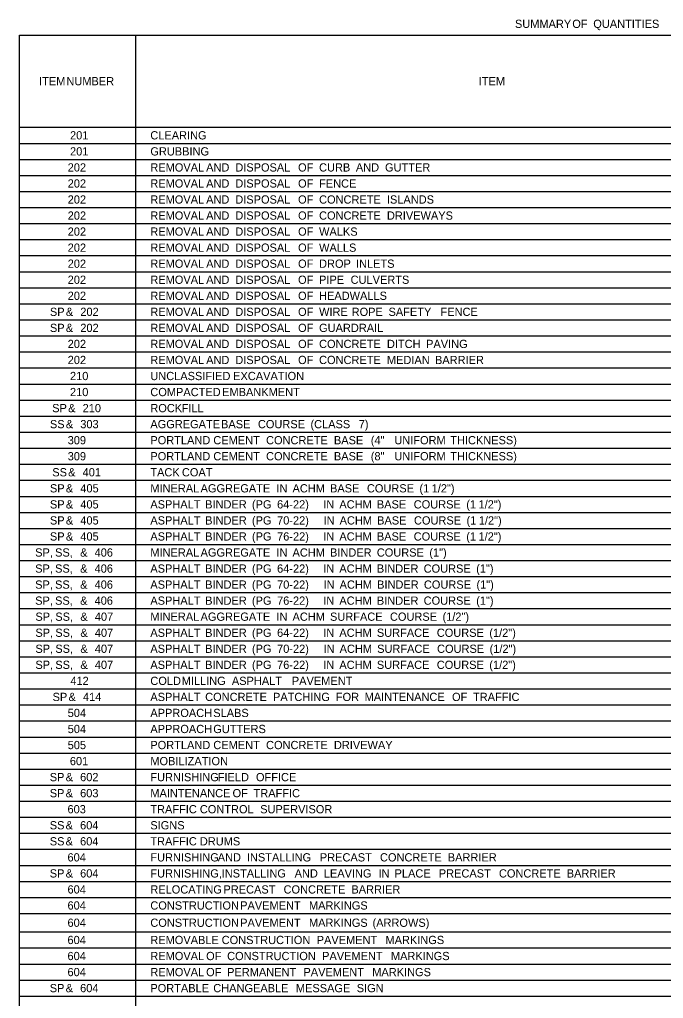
# Model space of a CAD drawing. Extents: x 1226603 to 1228117, y 151305 to 152343.
# Drawn here: x 1226606 to 1226938, y 151837 to 152343 of the extents above; entities that cross this region are included whole.
import ezdxf

# ---------------------------------------------------------------- set-up
doc = ezdxf.new("R2010")
doc.units = 0
doc.layers.add('R_Dimension', color=7, linetype='Continuous')

msp = doc.modelspace()

# ---------------------------------------------------------------- linework, layer by layer
at = {"layer": 'R_Dimension'}
for p, q in [((1226605.78, 152334.72), (1227235.63, 152334.72)), ((1226605.78, 151338.98), (1226605.78, 152334.72)), ((1226665.86, 151338.98), (1226665.86, 152334.72)), ((1226605.78, 152287.07), (1227235.63, 152287.07)), ((1226605.78, 152278.78), (1227235.63, 152278.78)), ((1226605.78, 152270.49), (1227235.63, 152270.49)), ((1226605.78, 152262.2), (1227235.63, 152262.2)), ((1226605.78, 152253.92), (1227235.63, 152253.92)), ((1226605.78, 152245.63), (1227235.63, 152245.63)), ((1226605.78, 152237.34), (1227235.63, 152237.34)), ((1226605.78, 152229.05), (1227235.63, 152229.05)), ((1226605.78, 152220.77), (1227235.63, 152220.77)), ((1226605.78, 152212.48), (1227235.63, 152212.48)), ((1226605.78, 152204.19), (1227235.63, 152204.19)), ((1226605.78, 152195.9), (1227235.63, 152195.9)), ((1226605.78, 152187.62), (1227235.63, 152187.62)), ((1226605.78, 152179.33), (1227235.63, 152179.33)), ((1226605.78, 152171.04), (1227235.63, 152171.04)), ((1226605.78, 152162.75), (1227235.63, 152162.75)), ((1226605.78, 152154.47), (1227235.63, 152154.47)), ((1226605.78, 152146.18), (1227235.63, 152146.18)), ((1226605.78, 152137.89), (1227235.63, 152137.89)), ((1226605.78, 152129.6), (1227235.63, 152129.6)), ((1226605.78, 152121.32), (1227235.63, 152121.32)), ((1226605.78, 152113.03), (1227235.63, 152113.03)), ((1226605.78, 152104.74), (1227235.63, 152104.74)), ((1226605.78, 152096.45), (1227235.63, 152096.45)), ((1226605.78, 152088.17), (1227235.63, 152088.17)), ((1226605.78, 152079.88), (1227235.63, 152079.88)), ((1226605.78, 152071.59), (1227235.63, 152071.59)), ((1226605.78, 152063.3), (1227235.63, 152063.3)), ((1226605.78, 152055.02), (1227235.63, 152055.02)), ((1226605.78, 152046.73), (1227235.63, 152046.73)), ((1226605.78, 152038.44), (1227235.63, 152038.44)), ((1226605.78, 152030.15), (1227235.63, 152030.15)), ((1226605.78, 152021.87), (1227235.63, 152021.87)), ((1226605.78, 152013.58), (1227235.63, 152013.58)), ((1226605.78, 152005.29), (1227235.63, 152005.29)), ((1226605.78, 151997), (1227235.63, 151997)), ((1226605.78, 151988.72), (1227235.63, 151988.72)), ((1226605.78, 151980.43), (1227235.63, 151980.43)), ((1226605.78, 151972.14), (1227235.63, 151972.14)), ((1226605.78, 151963.85), (1227235.63, 151963.85)), ((1226605.78, 151955.57), (1227235.63, 151955.57)), ((1226605.78, 151947.28), (1227235.63, 151947.28)), ((1226605.78, 151938.99), (1227235.63, 151938.99)), ((1226605.78, 151930.7), (1227235.63, 151930.7)), ((1226605.78, 151922.42), (1227235.63, 151922.42)), ((1226605.78, 151914.13), (1227235.63, 151914.13)), ((1226605.78, 151905.84), (1227235.63, 151905.84)), ((1226605.78, 151897.55), (1227235.63, 151897.55)), ((1226605.78, 151889.27), (1227235.63, 151889.27)), ((1226605.78, 151880.98), (1227235.63, 151880.98)), ((1226605.78, 151871.45), (1227235.63, 151871.45)), ((1226605.78, 151863.16), (1227235.63, 151863.16)), ((1226605.78, 151854.87), (1227235.63, 151854.87)), ((1226605.78, 151846.58), (1227235.63, 151846.58)), ((1226605.78, 151838.3), (1227235.63, 151838.3))]:
    msp.add_line(p, q, dxfattribs=at)

# ---------------------------------------------------------------- texts
for s, p in [('SUMMARY', (1226861.64, 152338.39)), (' OF', (1226889.68, 152338.39)), (' QUANTITIES', (1226900.52, 152338.39)), ('ITEM', (1226615.87, 152308.77)), (' NUMBER', (1226628.39, 152308.77)), ('ITEM', (1226842.96, 152308.77)), ('201', (1226631.84, 152280.8)), ('CLEARING', (1226673.32, 152280.8)), ('201', (1226631.84, 152272.51)), ('GRUBBING', (1226673.32, 152272.51)), ('202', (1226630.63, 152264.22)), ('REMOVAL', (1226673.32, 152264.22)), (' AND', (1226700.56, 152264.22)), (' DISPOSAL', (1226715.62, 152264.22)), (' OF', (1226748.05, 152264.22)), (' CURB', (1226758.89, 152264.22)), (' AND', (1226777.9, 152264.22)), (' GUTTER', (1226792.96, 152264.22)), ('202', (1226630.63, 152255.93)), ('REMOVAL', (1226673.32, 152255.93)), (' AND', (1226700.56, 152255.93)), (' DISPOSAL', (1226715.62, 152255.93)), (' OF', (1226748.05, 152255.93)), (' FENCE', (1226758.89, 152255.93)), ('202', (1226630.63, 152247.65)), ('REMOVAL', (1226673.32, 152247.65)), (' AND', (1226700.56, 152247.65)), (' DISPOSAL', (1226715.62, 152247.65)), (' OF', (1226748.05, 152247.65)), (' CONCRETE', (1226758.89, 152247.65)), (' ISLANDS', (1226793.93, 152247.65)), ('202', (1226630.63, 152239.36)), ('REMOVAL', (1226673.32, 152239.36)), (' AND', (1226700.56, 152239.36)), (' DISPOSAL', (1226715.62, 152239.36)), (' OF', (1226748.05, 152239.36)), (' CONCRETE', (1226758.89, 152239.36)), (' DRIVEWAYS', (1226793.93, 152239.36)), ('202', (1226630.63, 152231.07)), ('REMOVAL', (1226673.32, 152231.07)), (' AND', (1226700.56, 152231.07)), (' DISPOSAL', (1226715.62, 152231.07)), (' OF', (1226748.05, 152231.07)), (' WALKS', (1226758.89, 152231.07)), ('202', (1226630.63, 152222.78)), ('REMOVAL', (1226673.32, 152222.78)), (' AND', (1226700.56, 152222.78)), (' DISPOSAL', (1226715.62, 152222.78)), (' OF', (1226748.05, 152222.78)), (' WALLS', (1226758.89, 152222.78)), ('202', (1226630.63, 152214.5)), ('REMOVAL', (1226673.32, 152214.5)), (' AND', (1226700.56, 152214.5)), (' DISPOSAL', (1226715.62, 152214.5)), (' OF', (1226748.05, 152214.5)), (' DROP', (1226758.89, 152214.5)), (' INLETS', (1226777.96, 152214.5)), ('202', (1226630.63, 152206.21)), ('REMOVAL', (1226673.32, 152206.21)), (' AND', (1226700.56, 152206.21)), (' DISPOSAL', (1226715.62, 152206.21)), (' OF', (1226748.05, 152206.21)), (' PIPE', (1226758.89, 152206.21)), (' CULVERTS', (1226775.19, 152206.21)), ('202', (1226630.63, 152197.92)), ('REMOVAL', (1226673.32, 152197.92)), (' AND', (1226700.56, 152197.92)), (' DISPOSAL', (1226715.62, 152197.92)), (' OF', (1226748.05, 152197.92)), (' HEADWALLS', (1226758.89, 152197.92)), ('SP', (1226621.45, 152189.63)), (' &', (1226628.11, 152189.63)), (' 202', (1226635.57, 152189.63)), ('REMOVAL', (1226673.32, 152189.63)), (' AND', (1226700.56, 152189.63)), (' DISPOSAL', (1226715.62, 152189.63)), (' OF', (1226748.05, 152189.63)), (' WIRE', (1226758.89, 152189.63)), (' ROPE', (1226775.72, 152189.63)), (' SAFETY', (1226794.76, 152189.63)), (' FENCE', (1226821.63, 152189.63)), ('SP', (1226621.45, 152181.35)), (' &', (1226628.11, 152181.35)), (' 202', (1226635.57, 152181.35)), ('REMOVAL', (1226673.32, 152181.35)), (' AND', (1226700.56, 152181.35)), (' DISPOSAL', (1226715.62, 152181.35)), (' OF', (1226748.05, 152181.35)), (' GUARDRAIL', (1226758.89, 152181.35)), ('202', (1226630.63, 152173.06)), ('REMOVAL', (1226673.32, 152173.06)), (' AND', (1226700.56, 152173.06)), (' DISPOSAL', (1226715.62, 152173.06)), (' OF', (1226748.05, 152173.06)), (' CONCRETE', (1226758.89, 152173.06)), (' DITCH', (1226793.93, 152173.06)), (' PAVING', (1226814.17, 152173.06)), ('202', (1226630.63, 152164.77)), ('REMOVAL', (1226673.32, 152164.77)), (' AND', (1226700.56, 152164.77)), (' DISPOSAL', (1226715.62, 152164.77)), (' OF', (1226748.05, 152164.77)), (' CONCRETE', (1226758.89, 152164.77)), (' MEDIAN', (1226793.93, 152164.77)), (' BARRIER', (1226818.76, 152164.77)), ('210', (1226631.82, 152156.48)), ('UNCLASSIFIED', (1226673.32, 152156.48)), (' EXCAVATION', (1226714.51, 152156.48)), ('210', (1226631.82, 152148.2)), ('COMPACTED', (1226673.32, 152148.2)), (' EMBANKMENT', (1226708.83, 152148.2)), ('SP', (1226622.63, 152139.91)), (' &', (1226629.29, 152139.91)), (' 210', (1226636.76, 152139.91)), ('ROCK', (1226673.32, 152139.91)), (' FILL', (1226687.91, 152139.91)), ('SS', (1226621.46, 152131.62)), (' &', (1226628.09, 152131.62)), (' 303', (1226635.55, 152131.62)), ('AGGREGATE', (1226673.32, 152131.62)), (' BASE', (1226708.26, 152131.62)), (' COURSE', (1226727.3, 152131.62)), (' (CLASS', (1226754.44, 152131.62)), (' 7)', (1226779.37, 152131.62)), ('309', (1226630.62, 152123.33)), ('PORTLAND', (1226673.32, 152123.33)), (' CEMENT', (1226704.27, 152123.33)), (' CONCRETE', (1226731.51, 152123.33)), (' BASE', (1226766.55, 152123.33)), (' (4"', (1226785.59, 152123.33)), (' UNIFORM', (1226797.77, 152123.33)), (' THICKNESS)', (1226826.65, 152123.33)), ('309', (1226630.62, 152115.05)), ('PORTLAND', (1226673.32, 152115.05)), (' CEMENT', (1226704.27, 152115.05)), (' CONCRETE', (1226731.51, 152115.05)), (' BASE', (1226766.55, 152115.05)), (' (8"', (1226785.59, 152115.05)), (' UNIFORM', (1226797.77, 152115.05)), (' THICKNESS)', (1226826.65, 152115.05)), ('SS', (1226622.67, 152106.76)), (' &', (1226629.29, 152106.76)), (' 401', (1226636.76, 152106.76)), ('TACK', (1226673.32, 152106.76)), (' COAT', (1226688.04, 152106.76)), ('SP', (1226621.45, 152098.47)), (' &', (1226628.11, 152098.47)), (' 405', (1226635.57, 152098.47)), ('MINERAL', (1226673.32, 152098.47)), (' AGGREGATE', (1226697.68, 152098.47)), (' IN', (1226736.87, 152098.47)), (' ACHM', (1226745.17, 152098.47)), (' BASE', (1226764.54, 152098.47)), (' COURSE', (1226783.59, 152098.47)), (' (1', (1226810.73, 152098.47)), (' 1/2")', (1226817.05, 152098.47)), ('SP', (1226621.45, 152090.18)), (' &', (1226628.11, 152090.18)), (' 405', (1226635.57, 152090.18)), ('ASPHALT', (1226673.32, 152090.18)), (' BINDER', (1226700.06, 152090.18)), (' (PG', (1226724.22, 152090.18)), (' 64-22)', (1226737.2, 152090.18)), (' IN', (1226761.06, 152090.18)), (' ACHM', (1226769.36, 152090.18)), (' BASE', (1226788.74, 152090.18)), (' COURSE', (1226807.78, 152090.18)), (' (1', (1226834.92, 152090.18)), (' 1/2")', (1226841.25, 152090.18)), ('SP', (1226621.45, 152081.9)), (' &', (1226628.11, 152081.9)), (' 405', (1226635.57, 152081.9)), ('ASPHALT', (1226673.32, 152081.9)), (' BINDER', (1226700.06, 152081.9)), (' (PG', (1226724.22, 152081.9)), (' 70-22)', (1226737.2, 152081.9)), (' IN', (1226761.2, 152081.9)), (' ACHM', (1226769.5, 152081.9)), (' BASE', (1226788.87, 152081.9)), (' COURSE', (1226807.91, 152081.9)), (' (1', (1226835.05, 152081.9)), (' 1/2")', (1226841.38, 152081.9)), ('SP', (1226621.45, 152073.61)), (' &', (1226628.11, 152073.61)), (' 405', (1226635.57, 152073.61)), ('ASPHALT', (1226673.32, 152073.61)), (' BINDER', (1226700.06, 152073.61)), (' (PG', (1226724.22, 152073.61)), (' 76-22)', (1226737.2, 152073.61)), (' IN', (1226761.06, 152073.61)), (' ACHM', (1226769.36, 152073.61)), (' BASE', (1226788.74, 152073.61)), (' COURSE', (1226807.78, 152073.61)), (' (1', (1226834.92, 152073.61)), (' 1/2")', (1226841.25, 152073.61)), ('SP,', (1226613.83, 152065.32)), (' SS,', (1226622.53, 152065.32)), (' &', (1226635.48, 152065.32)), (' 406', (1226642.95, 152065.32)), ('MINERAL', (1226673.32, 152065.32)), (' AGGREGATE', (1226697.68, 152065.32)), (' IN', (1226736.87, 152065.32)), (' ACHM', (1226745.17, 152065.32)), (' BINDER', (1226764.54, 152065.32)), (' COURSE', (1226788.71, 152065.32)), (' (1")', (1226815.85, 152065.32)), ('SP,', (1226613.83, 152057.03)), (' SS,', (1226622.53, 152057.03)), (' &', (1226635.48, 152057.03)), (' 406', (1226642.95, 152057.03)), ('ASPHALT', (1226673.32, 152057.03)), (' BINDER', (1226700.06, 152057.03)), (' (PG', (1226724.22, 152057.03)), (' 64-22)', (1226737.2, 152057.03)), (' IN', (1226761.06, 152057.03)), (' ACHM', (1226769.36, 152057.03)), (' BINDER', (1226788.74, 152057.03)), (' COURSE', (1226812.9, 152057.03)), (' (1")', (1226840.04, 152057.03)), ('SP,', (1226613.83, 152048.75)), (' SS,', (1226622.53, 152048.75)), (' &', (1226635.48, 152048.75)), (' 406', (1226642.95, 152048.75)), ('ASPHALT', (1226673.32, 152048.75)), (' BINDER', (1226700.06, 152048.75)), (' (PG', (1226724.22, 152048.75)), (' 70-22)', (1226737.2, 152048.75)), (' IN', (1226761.2, 152048.75)), (' ACHM', (1226769.5, 152048.75)), (' BINDER', (1226788.87, 152048.75)), (' COURSE', (1226813.03, 152048.75)), (' (1")', (1226840.17, 152048.75)), ('SP,', (1226613.83, 152040.46)), (' SS,', (1226622.53, 152040.46)), (' &', (1226635.48, 152040.46)), (' 406', (1226642.95, 152040.46)), ('ASPHALT', (1226673.32, 152040.46)), (' BINDER', (1226700.06, 152040.46)), (' (PG', (1226724.22, 152040.46)), (' 76-22)', (1226737.2, 152040.46)), (' IN', (1226761.06, 152040.46)), (' ACHM', (1226769.36, 152040.46)), (' BINDER', (1226788.74, 152040.46)), (' COURSE', (1226812.9, 152040.46)), (' (1")', (1226840.04, 152040.46)), ('SP,', (1226613.95, 152032.17)), (' SS,', (1226622.65, 152032.17)), (' &', (1226635.6, 152032.17)), (' 407', (1226643.06, 152032.17)), ('MINERAL', (1226673.32, 152032.17)), (' AGGREGATE', (1226697.68, 152032.17)), (' IN', (1226736.87, 152032.17)), (' ACHM', (1226745.17, 152032.17)), (' SURFACE', (1226764.54, 152032.17)), (' COURSE', (1226795.5, 152032.17)), (' (1/2")', (1226822.64, 152032.17)), ('SP,', (1226613.95, 152023.88)), (' SS,', (1226622.65, 152023.88)), (' &', (1226635.6, 152023.88)), (' 407', (1226643.06, 152023.88)), ('ASPHALT', (1226673.32, 152023.88)), (' BINDER', (1226700.06, 152023.88)), (' (PG', (1226724.22, 152023.88)), (' 64-22)', (1226737.2, 152023.88)), (' IN', (1226761.06, 152023.88)), (' ACHM', (1226769.36, 152023.88)), (' SURFACE', (1226788.74, 152023.88)), (' COURSE', (1226819.69, 152023.88)), (' (1/2")', (1226846.83, 152023.88)), ('SP,', (1226613.95, 152015.6)), (' SS,', (1226622.65, 152015.6)), (' &', (1226635.6, 152015.6)), (' 407', (1226643.06, 152015.6)), ('ASPHALT', (1226673.32, 152015.6)), (' BINDER', (1226700.06, 152015.6)), (' (PG', (1226724.22, 152015.6)), (' 70-22)', (1226737.2, 152015.6)), (' IN', (1226761.2, 152015.6)), (' ACHM', (1226769.5, 152015.6)), (' SURFACE', (1226788.87, 152015.6)), (' COURSE', (1226819.83, 152015.6)), (' (1/2")', (1226846.97, 152015.6)), ('SP,', (1226613.95, 152007.31)), (' SS,', (1226622.65, 152007.31)), (' &', (1226635.6, 152007.31)), (' 407', (1226643.06, 152007.31)), ('ASPHALT', (1226673.32, 152007.31)), (' BINDER', (1226700.06, 152007.31)), (' (PG', (1226724.22, 152007.31)), (' 76-22)', (1226737.2, 152007.31)), (' IN', (1226761.06, 152007.31)), (' ACHM', (1226769.36, 152007.31)), (' SURFACE', (1226788.74, 152007.31)), (' COURSE', (1226819.69, 152007.31)), (' (1/2")', (1226846.83, 152007.31)), ('412', (1226632, 151999.02)), ('COLD', (1226673.32, 151999.02)), (' MILLING', (1226687.94, 151999.02)), (' ASPHALT', (1226713.85, 151999.02)), (' PAVEMENT', (1226744.83, 151999.02)), ('SP', (1226622.82, 151990.73)), (' &', (1226629.48, 151990.73)), (' 414', (1226636.94, 151990.73)), ('ASPHALT', (1226673.32, 151990.73)), (' CONCRETE', (1226700.06, 151990.73)), (' PATCHING', (1226735.1, 151990.73)), (' FOR', (1226767.56, 151990.73)), (' MAINTENANCE', (1226782.41, 151990.73)), (' OF', (1226827.56, 151990.73)), (' TRAFFIC', (1226838.4, 151990.73)), ('504', (1226630.63, 151982.45)), ('APPROACH', (1226673.32, 151982.45)), (' SLABS', (1226704.24, 151982.45)), ('504', (1226630.63, 151974.16)), ('APPROACH', (1226673.32, 151974.16)), (' GUTTERS', (1226704.24, 151974.16)), ('505', (1226630.63, 151965.87)), ('PORTLAND', (1226673.32, 151965.87)), (' CEMENT', (1226704.27, 151965.87)), (' CONCRETE', (1226731.51, 151965.87)), (' DRIVEWAY', (1226766.55, 151965.87)), ('601', (1226631.74, 151957.58)), ('MOBILIZATION', (1226673.32, 151957.58)), ('SP', (1226621.35, 151949.3)), (' &', (1226628.01, 151949.3)), (' 602', (1226635.47, 151949.3)), ('FURNISHING', (1226673.32, 151949.3)), (' FIELD', (1226706.55, 151949.3)), (' OFFICE', (1226726.29, 151949.3)), ('SP', (1226621.35, 151941.01)), (' &', (1226628.01, 151941.01)), (' 603', (1226635.47, 151941.01)), ('MAINTENANCE', (1226673.32, 151941.01)), (' OF', (1226714.21, 151941.01)), (' TRAFFIC', (1226725.06, 151941.01)), ('603', (1226630.53, 151932.72)), ('TRAFFIC', (1226673.32, 151932.72)), (' CONTROL', (1226697.31, 151932.72)), (' SUPERVISOR', (1226728.47, 151932.72)), ('SS', (1226621.36, 151924.43)), (' &', (1226627.99, 151924.43)), (' 604', (1226635.45, 151924.43)), ('SIGNS', (1226673.32, 151924.43)), ('SS', (1226621.36, 151916.15)), (' &', (1226627.99, 151916.15)), (' 604', (1226635.45, 151916.15)), ('TRAFFIC', (1226673.32, 151916.15)), (' DRUMS', (1226697.31, 151916.15)), ('604', (1226630.53, 151907.86)), ('FURNISHING', (1226673.32, 151907.86)), (' AND', (1226706.55, 151907.86)), (' INSTALLING', (1226721.61, 151907.86)), (' PRECAST', (1226759.29, 151907.86)), (' CONCRETE', (1226790.35, 151907.86)), (' BARRIER', (1226825.38, 151907.86)), ('SP', (1226621.35, 151899.57)), (' &', (1226628.01, 151899.57)), (' 604', (1226635.47, 151899.57)), ('FURNISHING,', (1226673.32, 151899.57)), (' INSTALLING', (1226708.59, 151899.57)), (' AND', (1226746.27, 151899.57)), (' LEAVING', (1226761.33, 151899.57)), (' IN', (1226789.58, 151899.57)), (' PLACE', (1226797.88, 151899.57)), (' PRECAST', (1226820.73, 151899.57)), (' CONCRETE', (1226851.79, 151899.57)), (' BARRIER', (1226886.82, 151899.57)), ('604', (1226630.53, 151891.28)), ('RELOCATING', (1226673.32, 151891.28)), (' PRECAST', (1226709.5, 151891.28)), (' CONCRETE', (1226740.55, 151891.28)), (' BARRIER', (1226775.59, 151891.28)), ('604', (1226630.53, 151883)), ('CONSTRUCTION', (1226673.32, 151883)), (' PAVEMENT', (1226718.13, 151883)), (' MARKINGS', (1226753.67, 151883)), ('604', (1226630.53, 151874.09)), ('CONSTRUCTION', (1226673.32, 151874.09)), (' PAVEMENT', (1226718.13, 151874.09)), (' MARKINGS', (1226753.67, 151874.09)), (' (ARROWS)', (1226786.5, 151874.09)), ('604', (1226630.53, 151865.18)), ('REMOVABLE', (1226673.32, 151865.18)), (' CONSTRUCTION', (1226708.59, 151865.18)), (' PAVEMENT', (1226757.65, 151865.18)), (' MARKINGS', (1226793.19, 151865.18)), ('604', (1226630.53, 151856.89)), ('REMOVAL', (1226673.32, 151856.89)), (' OF', (1226700.56, 151856.89)), (' CONSTRUCTION', (1226711.4, 151856.89)), (' PAVEMENT', (1226760.46, 151856.89)), (' MARKINGS', (1226796, 151856.89)), ('604', (1226630.53, 151848.6)), ('REMOVAL', (1226673.32, 151848.6)), (' OF', (1226700.56, 151848.6)), (' PERMANENT', (1226711.4, 151848.6)), (' PAVEMENT', (1226750.82, 151848.6)), (' MARKINGS', (1226786.36, 151848.6)), ('SP', (1226621.35, 151840.32)), (' &', (1226628.01, 151840.32)), (' 604', (1226635.47, 151840.32)), ('PORTABLE', (1226673.32, 151840.32)), (' CHANGEABLE', (1226704.24, 151840.32)), (' MESSAGE', (1226746.91, 151840.32)), (' SIGN', (1226778.33, 151840.32))]:
    msp.add_text(s, height=4.25, dxfattribs=at).set_placement(p)

doc.saveas('drawing.dxf')
